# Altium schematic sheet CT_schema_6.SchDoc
size 227 x 258 mm
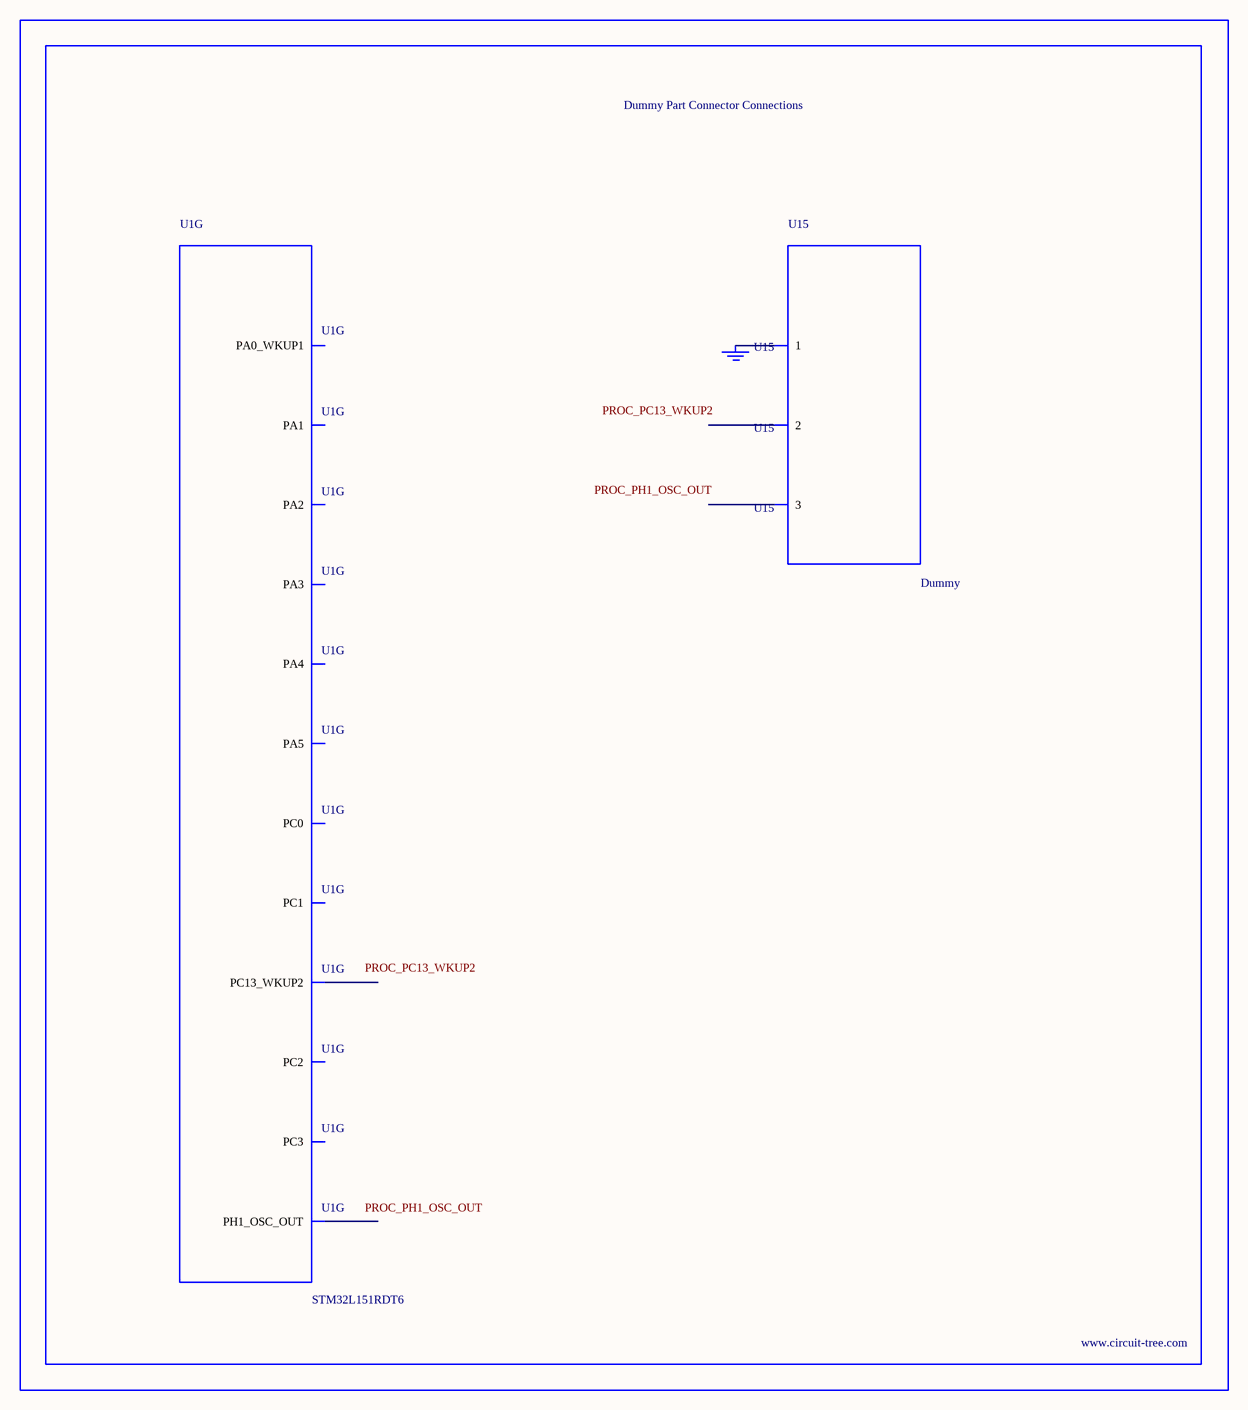
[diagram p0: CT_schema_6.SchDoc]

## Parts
BORDER5  (no value)
GND_INSTANCE_5_0  (no value)
U1  STM32L151RDT6  [LQFP64]  (part G of 7)
U15  Dummy  [DUMMY_PACKAGE_144]

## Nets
NetGND_INSTANCE_5_0_0: GND_INSTANCE_5_0.0(GND) U15.1

Not connected (* = marked no-connect by the designer): U1 2(PC13_WKUP2) 6(PH1_OSC_OUT) 8(PC0) 9(PC1) 10(PC2) 11(PC3) 14(PA0_WKUP1) 15(PA1) 16(PA2) 17(PA3) 20(PA4) 21(PA5); U15 2 3

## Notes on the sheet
- Labels drawn without touching a wire or pin: PROC_PC13_WKUP2, PROC_PH1_OSC_OUT

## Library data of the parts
BORDER5 = BORDER_PAGE5
GND_INSTANCE_5_0 = GND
